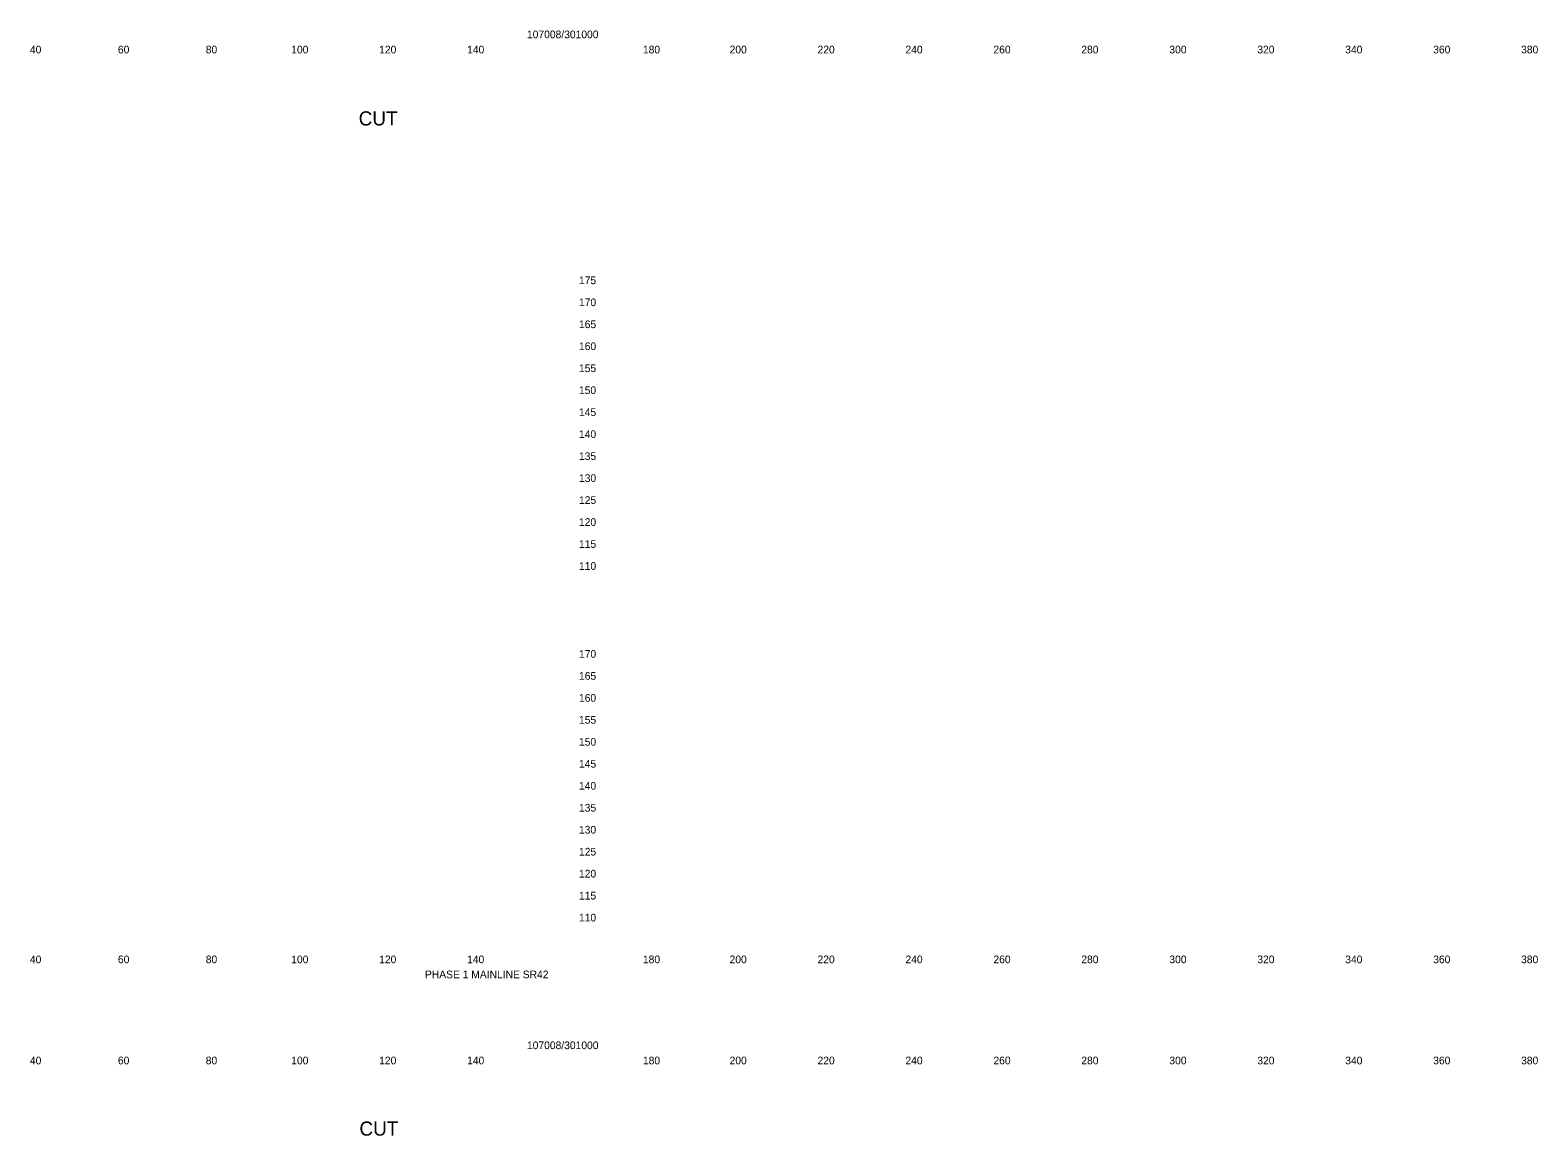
# Model space of a CAD drawing. Extents: x 21281 to 22024, y 6472 to 15198.
# Drawn here: x 21681.3 to 22024.2, y 10576.1 to 10827.6 of the extents above; entities that cross this region are included whole.
import ezdxf

# ---------------------------------------------------------------- set-up
doc = ezdxf.new("R2010")
doc.units = 0
doc.layers.add('XS_SHEET_LABELS_ELEVATION', color=7, linetype='Continuous')
doc.layers.add('XS_SHEET_LABELS_OFFSET', color=7, linetype='Continuous')

msp = doc.modelspace()

# ---------------------------------------------------------------- texts
at = {"layer": 'XS_SHEET_LABELS_ELEVATION'}
for s, p in [('  175  ', (21804.84, 10769.84)), ('  170  ', (21804.84, 10764.84)), ('  165  ', (21804.84, 10759.84)), ('  160  ', (21804.84, 10754.84)), ('  155  ', (21804.84, 10749.84)), ('  150  ', (21804.84, 10744.84)), ('  145  ', (21804.84, 10739.84)), ('  140  ', (21804.84, 10734.84)), ('  135  ', (21804.84, 10729.84)), ('  130  ', (21804.84, 10724.84)), ('  125  ', (21804.84, 10719.84)), ('  120  ', (21804.84, 10714.84)), ('  115  ', (21804.84, 10709.84)), ('  110  ', (21804.84, 10704.84)), ('  170  ', (21804.84, 10684.84)), ('  165  ', (21804.84, 10679.84)), ('  160  ', (21804.84, 10674.84)), ('  155  ', (21804.84, 10669.84)), ('  150  ', (21804.84, 10664.84)), ('  145  ', (21804.84, 10659.84)), ('  140  ', (21804.84, 10654.84)), ('  135  ', (21804.84, 10649.84)), ('  130  ', (21804.84, 10644.84)), ('  125  ', (21804.84, 10639.84)), ('  120  ', (21804.84, 10634.84)), ('  115  ', (21804.84, 10629.84)), ('  110  ', (21804.84, 10624.84))]:
    msp.add_text(s, height=1.75, dxfattribs=at).set_placement(p)
at = {"layer": 'XS_SHEET_LABELS_OFFSET'}
for s, height, p in [('107008/301000', 1.75, (21794.31, 10825.79)), ('  40  ', 1.75, (21679.95, 10822.34)), ('  60  ', 1.75, (21699.97, 10822.34)), ('  80  ', 1.75, (21719.95, 10822.34)), ('  100  ', 1.75, (21739.39, 10822.34)), ('  120  ', 1.75, (21759.39, 10822.34)), ('  140  ', 1.75, (21779.39, 10822.34)), ('  180  ', 1.75, (21819.39, 10822.34)), ('  200  ', 1.75, (21839.1, 10822.34)), ('  220  ', 1.75, (21859.1, 10822.34)), ('  240  ', 1.75, (21879.1, 10822.34)), ('  260  ', 1.75, (21899.11, 10822.34)), ('  280  ', 1.75, (21919.1, 10822.34)), ('  300  ', 1.75, (21939.13, 10822.34)), ('  320  ', 1.75, (21959.13, 10822.34)), ('  340  ', 1.75, (21979.13, 10822.34)), ('  360  ', 1.75, (21999.14, 10822.34)), ('  380  ', 1.75, (22019.13, 10822.34)), ('CUT', 3.222, (21756.03, 10805.94)), ('  40  ', 1.75, (21679.95, 10615.34)), ('  60  ', 1.75, (21699.97, 10615.34)), ('  80  ', 1.75, (21719.95, 10615.34)), ('  100  ', 1.75, (21739.39, 10615.34)), ('  120  ', 1.75, (21759.39, 10615.34)), ('  140  ', 1.75, (21779.39, 10615.34)), ('  180  ', 1.75, (21819.39, 10615.34)), ('  200  ', 1.75, (21839.1, 10615.34)), ('  220  ', 1.75, (21859.1, 10615.34)), ('  240  ', 1.75, (21879.1, 10615.34)), ('  260  ', 1.75, (21899.11, 10615.34)), ('  280  ', 1.75, (21919.1, 10615.34)), ('  300  ', 1.75, (21939.13, 10615.34)), ('  320  ', 1.75, (21959.13, 10615.34)), ('  340  ', 1.75, (21979.13, 10615.34)), ('  360  ', 1.75, (21999.14, 10615.34)), ('  380  ', 1.75, (22019.13, 10615.34)), ('PHASE 1 MAINLINE SR42', 1.75, (21771.11, 10611.92)), ('107008/301000', 1.75, (21794.31, 10595.79)), ('  40  ', 1.75, (21679.95, 10592.34)), ('  60  ', 1.75, (21699.97, 10592.34)), ('  80  ', 1.75, (21719.95, 10592.34)), ('  100  ', 1.75, (21739.39, 10592.34)), ('  120  ', 1.75, (21759.39, 10592.34)), ('  140  ', 1.75, (21779.39, 10592.34)), ('  180  ', 1.75, (21819.39, 10592.34)), ('  200  ', 1.75, (21839.1, 10592.34)), ('  220  ', 1.75, (21859.1, 10592.34)), ('  240  ', 1.75, (21879.1, 10592.34)), ('  260  ', 1.75, (21899.11, 10592.34)), ('  280  ', 1.75, (21919.1, 10592.34)), ('  300  ', 1.75, (21939.13, 10592.34)), ('  320  ', 1.75, (21959.13, 10592.34)), ('  340  ', 1.75, (21979.13, 10592.34)), ('  360  ', 1.75, (21999.14, 10592.34)), ('  380  ', 1.75, (22019.13, 10592.34)), ('CUT', 3.222, (21756.2, 10576.11))]:
    msp.add_text(s, height=height, dxfattribs=at).set_placement(p)

doc.saveas('drawing.dxf')
